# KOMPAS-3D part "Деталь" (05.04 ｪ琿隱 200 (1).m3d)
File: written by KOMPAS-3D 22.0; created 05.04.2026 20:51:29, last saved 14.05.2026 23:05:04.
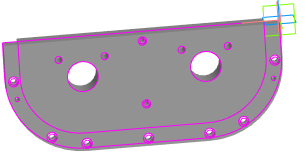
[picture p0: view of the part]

Document properties: Автор: taras; Полное имя файла: E:\test_kompas\all_v20\05.04 крышка200 (1).m3d

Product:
- Part/product: Деталь
    Масса: 19.948382

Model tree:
1. Эскиз:3
2. Элемент выдавливания:24
     Расстояние 1 = 20
3. Элемент выдавливания:25
     Расстояние 1 = -20
4. Эскиз:4  (with: Элемент выдавливания:24)
5. Элемент выдавливания:26
     Расстояние 1 = -40
6. Элемент выдавливания:27
     Расстояние 1 = -40
7. Элемент выдавливания:28
     Расстояние 2 = 40
8. Элемент выдавливания:29
     Расстояние 2 = 11
9. Элемент выдавливания:30
     Расстояние 2 = 20
10. Элемент выдавливания:31
     Расстояние 2 = 20
11. Элемент выдавливания:32
     Расстояние 2 = 30
12. Элемент выдавливания:35
     Расстояние 2 = 20
13. Элемент выдавливания:36
     Расстояние 2 = 10
14. Элемент выдавливания:37
     Расстояние 2 = 40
